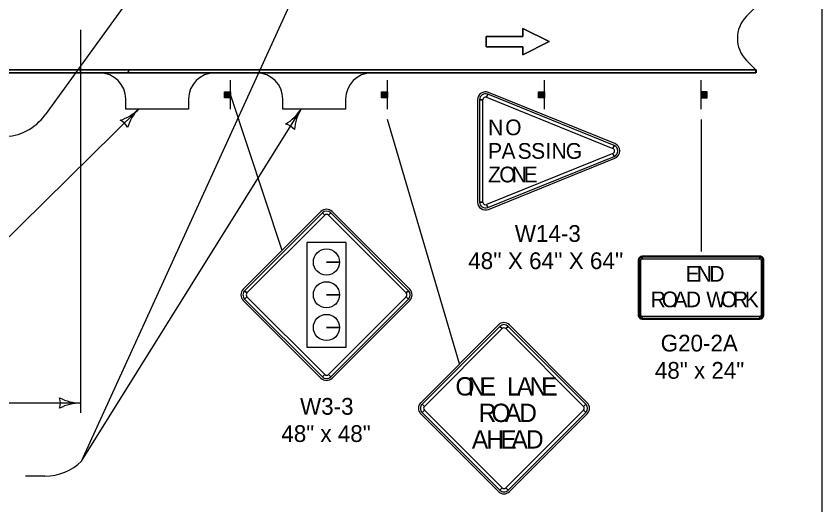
# Model space of a CAD drawing. Extents: x -2134934 to -2122394, y -2139046 to -2137036.
# Drawn here: x -2127867 to -2127097, y -2138081 to -2137614 of the extents above; entities that cross this region are included whole.
import ezdxf

# ---------------------------------------------------------------- set-up
doc = ezdxf.new("R2010")
doc.units = 0
for name, color, linetype in [('Barrier', 7, 'Continuous'), ('BridgeSuperStructureExisting', 7, 'Continuous'), ('Default', 7, 'Continuous'), ('DsnShtPlotIdentification', 7, 'Continuous'), ('DsnShtPlotShape', 7, 'Continuous')]:
    doc.layers.add(name, color=color, linetype=linetype)

msp = doc.modelspace()

# ---------------------------------------------------------------- linework, layer by layer
at = {"layer": 'Barrier'}
for p, q in [((-2127417.35, -2137691.45), (-2127416.18, -2137688.56)), ((-2127294.65, -2137735.69), (-2127415.48, -2137686.82)), ((-2127425.79, -2137693.77), (-2127425.79, -2137791.52)), ((-2127423.92, -2137693.77), (-2127420.79, -2137693.77)), ((-2127295.36, -2137737.43), (-2127296.53, -2137740.33)), ((-2127296.53, -2137744.96), (-2127295.36, -2137747.86)), ((-2127415.48, -2137798.48), (-2127294.65, -2137749.6)), ((-2127420.79, -2137791.52), (-2127423.92, -2137791.52)), ((-2127575.46, -2137800.5), (-2127649.71, -2137874.75)), ((-2127490.61, -2137874.75), (-2127564.86, -2137800.5)), ((-2127416.18, -2137796.74), (-2127417.35, -2137793.84)), ((-2127574.14, -2137801.83), (-2127571.93, -2137804.03)), ((-2127568.39, -2137804.03), (-2127566.18, -2137801.83)), ((-2127156.17, -2137843.14), (-2127268.67, -2137843.14)), ((-2127268.67, -2137845.64), (-2127268.67, -2137844.08)), ((-2127156.17, -2137844.08), (-2127156.17, -2137845.64)), ((-2127557.75, -2137848.72), (-2127570.25, -2137848.72)), ((-2127570.25, -2137848.72), (-2127557.75, -2137848.72)), ((-2127272.42, -2137846.89), (-2127272.42, -2137899.39)), ((-2127271.48, -2137846.89), (-2127269.92, -2137846.89)), ((-2127154.92, -2137846.89), (-2127153.35, -2137846.89)), ((-2127152.42, -2137899.39), (-2127152.42, -2137846.89)), ((-2127646.17, -2137878.28), (-2127648.38, -2137876.07)), ((-2127491.94, -2137876.07), (-2127494.14, -2137878.28)), ((-2127648.38, -2137884.03), (-2127646.17, -2137881.82)), ((-2127557.75, -2137879.97), (-2127570.25, -2137879.97)), ((-2127570.25, -2137879.97), (-2127557.75, -2137879.97)), ((-2127494.14, -2137881.82), (-2127491.94, -2137884.03)), ((-2127649.71, -2137885.35), (-2127575.46, -2137959.6)), ((-2127564.86, -2137959.6), (-2127490.61, -2137885.35)), ((-2127269.92, -2137899.39), (-2127271.48, -2137899.39)), ((-2127153.35, -2137899.39), (-2127154.92, -2137899.39)), ((-2127268.67, -2137902.2), (-2127268.67, -2137900.64)), ((-2127268.67, -2137903.14), (-2127156.17, -2137903.14)), ((-2127156.17, -2137900.64), (-2127156.17, -2137902.2)), ((-2127557.75, -2137911.22), (-2127570.25, -2137911.22)), ((-2127570.25, -2137911.22), (-2127557.75, -2137911.22)), ((-2127405.98, -2137908.8), (-2127480.23, -2137983.04)), ((-2127404.66, -2137910.12), (-2127402.45, -2137912.33)), ((-2127398.91, -2137912.33), (-2127396.7, -2137910.12)), ((-2127321.13, -2137983.04), (-2127395.38, -2137908.8)), ((-2127571.93, -2137956.06), (-2127574.14, -2137958.27)), ((-2127566.18, -2137958.27), (-2127568.39, -2137956.06)), ((-2127476.7, -2137986.58), (-2127478.9, -2137984.37)), ((-2127322.46, -2137984.37), (-2127324.67, -2137986.58)), ((-2127478.9, -2137992.32), (-2127476.7, -2137990.11)), ((-2127324.67, -2137990.11), (-2127322.46, -2137992.32)), ((-2127480.23, -2137993.65), (-2127405.98, -2138067.9)), ((-2127395.38, -2138067.9), (-2127321.13, -2137993.65)), ((-2127402.45, -2138064.36), (-2127404.66, -2138066.57)), ((-2127396.7, -2138066.57), (-2127398.91, -2138064.36))]:
    msp.add_line(p, q, dxfattribs=at)
for points in [[(-2127295.36, -2137737.43), (-2127416.18, -2137688.56), (-2127417.35, -2137691.45), (-2127296.53, -2137740.33), (-2127295.36, -2137737.43)], [(-2127423.92, -2137693.77), (-2127423.92, -2137791.52), (-2127420.79, -2137791.52), (-2127420.79, -2137693.77), (-2127423.92, -2137693.77)], [(-2127416.18, -2137796.74), (-2127295.36, -2137747.86), (-2127296.53, -2137744.96), (-2127417.35, -2137793.84), (-2127416.18, -2137796.74)], [(-2127574.14, -2137801.83), (-2127648.38, -2137876.07), (-2127646.17, -2137878.28), (-2127571.93, -2137804.03), (-2127574.14, -2137801.83)], [(-2127491.94, -2137876.07), (-2127566.18, -2137801.83), (-2127568.39, -2137804.03), (-2127494.14, -2137878.28), (-2127491.94, -2137876.07)], [(-2127551.43, -2137830.1), (-2127588.89, -2137830.1), (-2127588.89, -2137929.99), (-2127551.43, -2137929.99), (-2127551.43, -2137830.1)], [(-2127156.17, -2137844.08), (-2127268.67, -2137844.08), (-2127268.67, -2137845.64), (-2127156.17, -2137845.64), (-2127156.17, -2137844.08)], [(-2127271.48, -2137846.89), (-2127271.48, -2137899.39), (-2127269.92, -2137899.39), (-2127269.92, -2137846.89), (-2127271.48, -2137846.89)], [(-2127153.35, -2137899.39), (-2127153.35, -2137846.89), (-2127154.92, -2137846.89), (-2127154.92, -2137899.39), (-2127153.35, -2137899.39)], [(-2127648.38, -2137884.03), (-2127574.14, -2137958.27), (-2127571.93, -2137956.06), (-2127646.17, -2137881.82), (-2127648.38, -2137884.03)], [(-2127566.18, -2137958.27), (-2127491.94, -2137884.03), (-2127494.14, -2137881.82), (-2127568.39, -2137956.06), (-2127566.18, -2137958.27)], [(-2127268.67, -2137902.2), (-2127156.17, -2137902.2), (-2127156.17, -2137900.64), (-2127268.67, -2137900.64), (-2127268.67, -2137902.2)], [(-2127404.66, -2137910.12), (-2127478.9, -2137984.37), (-2127476.7, -2137986.58), (-2127402.45, -2137912.33), (-2127404.66, -2137910.12)], [(-2127322.46, -2137984.37), (-2127396.7, -2137910.12), (-2127398.91, -2137912.33), (-2127324.67, -2137986.58), (-2127322.46, -2137984.37)], [(-2127478.9, -2137992.32), (-2127404.66, -2138066.57), (-2127402.45, -2138064.36), (-2127476.7, -2137990.11), (-2127478.9, -2137992.32)], [(-2127396.7, -2138066.57), (-2127322.46, -2137992.32), (-2127324.67, -2137990.11), (-2127398.91, -2138064.36), (-2127396.7, -2138066.57)]]:
    msp.add_lwpolyline(points, close=True, dxfattribs=at)
for centre in [(-2127570.25, -2137848.72), (-2127570.25, -2137879.97), (-2127570.25, -2137911.22)]:
    msp.add_circle(centre, 12.5, dxfattribs=at)
for centre, radius, start, end in [((-2127418.29, -2137693.77), 7.5, 67.97571, 179.99985), ((-2127418.29, -2137693.77), 5.62, 67.97571, 179.99985), ((-2127418.29, -2137693.77), 2.5, 67.97571, 179.99985), ((-2127297.47, -2137742.65), 5.62, 292.02456, 67.97541), ((-2127297.47, -2137742.65), 7.5, 292.02456, 67.97598), ((-2127297.47, -2137742.65), 2.5, 292.02456, 67.97541), ((-2127418.29, -2137791.52), 7.5, 179.99985, 292.02456), ((-2127418.29, -2137791.52), 5.62, 179.99985, 292.02456), ((-2127418.29, -2137791.52), 2.5, 179.99985, 292.02456), ((-2127570.16, -2137805.8), 7.5, 44.99999, 134.99974), ((-2127570.16, -2137805.8), 5.62, 44.99999, 134.99974), ((-2127570.16, -2137805.8), 2.5, 44.99999, 134.99974), ((-2127268.67, -2137846.89), 3.75, 90.00021, 179.99985), ((-2127268.67, -2137846.89), 2.81, 90.00021, 179.99985), ((-2127268.67, -2137846.89), 1.25, 90.00021, 179.99985), ((-2127156.17, -2137846.89), 3.75, 0, 90.00021), ((-2127156.17, -2137846.89), 2.81, 0, 90.00021), ((-2127156.17, -2137846.89), 1.25, 0, 90.00021), ((-2127644.41, -2137880.05), 7.5, 134.99974, 224.99995), ((-2127644.41, -2137880.05), 5.62, 134.99974, 224.99995), ((-2127495.91, -2137880.05), 5.62, 315.00016, 44.9998), ((-2127495.91, -2137880.05), 7.5, 315.00016, 44.9998), ((-2127644.41, -2137880.05), 2.5, 134.99974, 224.99995), ((-2127495.91, -2137880.05), 2.5, 315.00016, 44.9998), ((-2127268.67, -2137899.39), 3.75, 179.99985, 270.00006), ((-2127268.67, -2137899.39), 2.81, 179.99985, 270.00006), ((-2127268.67, -2137899.39), 1.25, 179.99985, 270.00006), ((-2127156.17, -2137899.39), 3.75, 270.00006, 0.00027), ((-2127156.17, -2137899.39), 2.81, 270.00006, 0.00027), ((-2127156.17, -2137899.39), 1.25, 270.00006, 0.00027), ((-2127400.68, -2137914.1), 7.5, 44.99999, 134.99974), ((-2127400.68, -2137914.1), 5.62, 44.99999, 134.99974), ((-2127400.68, -2137914.1), 2.5, 44.99999, 134.99974), ((-2127570.16, -2137954.29), 7.5, 224.99995, 315.00016), ((-2127570.16, -2137954.29), 5.62, 224.99995, 315.00016), ((-2127570.16, -2137954.29), 2.5, 224.99995, 315.00016), ((-2127474.93, -2137988.35), 7.5, 134.99974, 224.99995), ((-2127474.93, -2137988.35), 5.62, 134.99974, 224.99995), ((-2127326.44, -2137988.35), 5.62, 315.00016, 44.9998), ((-2127326.44, -2137988.35), 7.5, 315.00016, 44.9998), ((-2127474.93, -2137988.35), 2.5, 134.99974, 224.99995), ((-2127326.44, -2137988.35), 2.5, 315.00016, 44.9998), ((-2127400.68, -2138062.59), 7.5, 224.99995, 315.00016), ((-2127400.68, -2138062.59), 5.62, 224.99995, 315.00016), ((-2127400.68, -2138062.59), 2.5, 224.99995, 315.00016)]:
    msp.add_arc(centre, radius, start, end, dxfattribs=at)
at = {"layer": 'BridgeSuperStructureExisting'}
for p, q in [((-2127686.42, -2137497.23), (-2127838.98, -2137708.29)), ((-2127804.12, -2138038.74), (-2127571.87, -2137530.07)), ((-2127168.91, -2137613.95), (-2127151.33, -2137596.37)), ((-2127805.12, -2137627.09), (-2127805.12, -2137992.63)), ((-2127160.12, -2137665.16), (-2127168.91, -2137656.37)), ((-2127168.9, -2137656.38), (-2127160.12, -2137665.16)), ((-2128470.12, -2137665.16), (-2127160.12, -2137665.16)), ((-2127786.92, -2137668.16), (-2127676.92, -2137668.16)), ((-2127636.92, -2137668.16), (-2127526.92, -2137668.16)), ((-2127661.96, -2137702.66), (-2127661.96, -2137675.16)), ((-2127511.96, -2137702.66), (-2127511.96, -2137675.16)), ((-2127361.96, -2137702.66), (-2127361.96, -2137675.16)), ((-2127212.15, -2137702.66), (-2127212.15, -2137675.16)), ((-2127667.28, -2137691.8), (-2127667.28, -2137686.21)), ((-2127666.96, -2137686.21), (-2127666.96, -2137691.8)), ((-2127666.74, -2137691.8), (-2127666.74, -2137686.21)), ((-2127666.42, -2137686.21), (-2127666.42, -2137691.8)), ((-2127666.19, -2137691.8), (-2127666.21, -2137686.21)), ((-2127665.78, -2137686.21), (-2127665.76, -2137691.8)), ((-2127665.56, -2137691.8), (-2127665.56, -2137686.21)), ((-2127665.13, -2137686.21), (-2127665.13, -2137691.8)), ((-2127664.75, -2137691.8), (-2127664.75, -2137686.21)), ((-2127664.43, -2137686.21), (-2127664.41, -2137691.8)), ((-2127664.21, -2137691.8), (-2127664.21, -2137686.21)), ((-2127663.94, -2137686.21), (-2127663.94, -2137691.8)), ((-2127663.61, -2137691.8), (-2127663.61, -2137686.21)), ((-2127663.4, -2137686.21), (-2127663.4, -2137691.8)), ((-2127663.18, -2137691.8), (-2127663.18, -2137686.21)), ((-2127662.91, -2137686.21), (-2127662.91, -2137691.8)), ((-2127662.65, -2137691.8), (-2127662.65, -2137686.21)), ((-2127662.37, -2137686.21), (-2127662.37, -2137691.8)), ((-2127612.59, -2137837.62), (-2127661.96, -2137688.91)), ((-2127517.28, -2137691.8), (-2127517.28, -2137686.21)), ((-2127516.96, -2137686.21), (-2127516.96, -2137691.8)), ((-2127516.74, -2137691.8), (-2127516.74, -2137686.21)), ((-2127516.42, -2137686.21), (-2127516.42, -2137691.8)), ((-2127516.19, -2137691.8), (-2127516.21, -2137686.21)), ((-2127515.78, -2137686.21), (-2127515.76, -2137691.8)), ((-2127515.56, -2137691.8), (-2127515.56, -2137686.21)), ((-2127515.13, -2137686.21), (-2127515.13, -2137691.8)), ((-2127514.75, -2137691.8), (-2127514.75, -2137686.21)), ((-2127514.43, -2137686.21), (-2127514.41, -2137691.8)), ((-2127514.21, -2137691.8), (-2127514.21, -2137686.21)), ((-2127513.94, -2137686.21), (-2127513.94, -2137691.8)), ((-2127513.61, -2137691.8), (-2127513.61, -2137686.21)), ((-2127513.4, -2137686.21), (-2127513.4, -2137691.8)), ((-2127513.18, -2137691.8), (-2127513.18, -2137686.21)), ((-2127512.91, -2137686.21), (-2127512.91, -2137691.8)), ((-2127512.65, -2137691.8), (-2127512.65, -2137686.21)), ((-2127512.37, -2137686.21), (-2127512.37, -2137691.8)), ((-2127367.28, -2137691.8), (-2127367.28, -2137686.21)), ((-2127366.96, -2137686.21), (-2127366.96, -2137691.8)), ((-2127366.74, -2137691.8), (-2127366.74, -2137686.21)), ((-2127366.42, -2137686.21), (-2127366.42, -2137691.8)), ((-2127366.19, -2137691.8), (-2127366.21, -2137686.21)), ((-2127365.78, -2137686.21), (-2127365.76, -2137691.8)), ((-2127365.56, -2137691.8), (-2127365.56, -2137686.21)), ((-2127365.13, -2137686.21), (-2127365.13, -2137691.8)), ((-2127364.75, -2137691.8), (-2127364.75, -2137686.21)), ((-2127364.43, -2137686.21), (-2127364.41, -2137691.8)), ((-2127364.21, -2137691.8), (-2127364.21, -2137686.21)), ((-2127363.94, -2137686.21), (-2127363.94, -2137691.8)), ((-2127363.61, -2137691.8), (-2127363.61, -2137686.21)), ((-2127363.4, -2137686.21), (-2127363.4, -2137691.8)), ((-2127363.18, -2137691.8), (-2127363.18, -2137686.21)), ((-2127362.91, -2137686.21), (-2127362.91, -2137691.8)), ((-2127362.65, -2137691.8), (-2127362.65, -2137686.21)), ((-2127362.37, -2137686.21), (-2127362.37, -2137691.8)), ((-2127211.73, -2137686.21), (-2127211.73, -2137691.8)), ((-2127211.45, -2137691.8), (-2127211.45, -2137686.21)), ((-2127211.19, -2137686.21), (-2127211.19, -2137691.8)), ((-2127210.93, -2137691.8), (-2127210.93, -2137686.21)), ((-2127210.7, -2137686.21), (-2127210.7, -2137691.8)), ((-2127210.5, -2137691.8), (-2127210.5, -2137686.21)), ((-2127210.16, -2137686.21), (-2127210.16, -2137691.8)), ((-2127209.9, -2137691.8), (-2127209.9, -2137686.21)), ((-2127209.67, -2137686.21), (-2127209.69, -2137691.8)), ((-2127209.35, -2137691.8), (-2127209.35, -2137686.21)), ((-2127208.98, -2137686.21), (-2127208.98, -2137691.8)), ((-2127208.55, -2137691.8), (-2127208.55, -2137686.21)), ((-2127208.32, -2137686.21), (-2127208.34, -2137691.8)), ((-2127207.91, -2137691.8), (-2127207.89, -2137686.21)), ((-2127207.68, -2137686.21), (-2127207.68, -2137691.8)), ((-2127207.36, -2137691.8), (-2127207.36, -2137686.21)), ((-2127207.14, -2137686.21), (-2127207.14, -2137691.8)), ((-2127206.82, -2137691.8), (-2127206.82, -2137686.21)), ((-2127937.83, -2137887.94), (-2127749.7, -2137702.65)), ((-2127804.12, -2138038.74), (-2127594.47, -2137702.65)), ((-2127443.11, -2137945.92), (-2127511.96, -2137712.66)), ((-2127211.96, -2137838.71), (-2127211.96, -2137712.66)), ((-2127805.12, -2137983.33), (-2128464.54, -2137983.33)), ((-2127839.21, -2138053.11), (-2127857.67, -2138053.11))]:
    msp.add_line(p, q, dxfattribs=at)
for points in [[(-2127417.52, -2137633.32), (-2127417.52, -2137643.32), (-2127382.52, -2137643.32), (-2127382.52, -2137650.82), (-2127357.52, -2137638.32), (-2127382.52, -2137625.82), (-2127382.52, -2137633.32)], [(-2127662.05, -2137686.21), (-2127662.05, -2137691.84), (-2127667.68, -2137691.84), (-2127667.68, -2137686.21)], [(-2127512.05, -2137686.21), (-2127512.05, -2137691.84), (-2127517.68, -2137691.84), (-2127517.68, -2137686.21)], [(-2127362.05, -2137686.21), (-2127362.05, -2137691.84), (-2127367.68, -2137691.84), (-2127367.68, -2137686.21)], [(-2127212.05, -2137686.21), (-2127212.05, -2137691.84), (-2127206.43, -2137691.84), (-2127206.43, -2137686.21)]]:
    msp.add_lwpolyline(points, close=True, dxfattribs=at)
for points in [[(-2127382.52, -2137633.32), (-2127382.52, -2137625.82), (-2127357.52, -2137638.32), (-2127382.52, -2137650.82), (-2127382.52, -2137643.32), (-2127417.52, -2137643.32), (-2127417.52, -2137633.32), (-2127382.52, -2137633.32)], [(-2127701.92, -2137693.16), (-2127701.92, -2137702.65), (-2127761.92, -2137702.65), (-2127761.92, -2137693.16)], [(-2127551.92, -2137693.16), (-2127551.92, -2137702.65), (-2127611.92, -2137702.65), (-2127611.92, -2137693.16)]]:
    msp.add_lwpolyline(points, dxfattribs=at)
for centre, radius, start, end in [((-2127147.69, -2137635.16), 30, 135, 225), ((-2127147.69, -2137635.16), 30, 135, 225), ((-2127786.92, -2137693.16), 25, 0, 90), ((-2127676.92, -2137693.16), 25, 90, 180), ((-2127636.92, -2137693.16), 25, 0, 90), ((-2127526.92, -2137693.16), 25, 90, 180), ((-2127879.5, -2137678.99), 50, 270, 324.13795), ((-2127839.21, -2138003.11), 50, 270, 314.56349)]:
    msp.add_arc(centre, radius, start, end, dxfattribs=at)
at = {"layer": 'Default'}
msp.add_lwpolyline([(-2130231.95, -2137035.95), (-2127096.96, -2137035.95), (-2127096.96, -2139045.94), (-2130231.95, -2139045.94)], close=True, dxfattribs=at)
at = {"layer": 'DsnShtPlotIdentification'}
for p, q in [((-2128660.12, -2137665.16), (-2127159.5, -2137665.16)), ((-2127805.12, -2137665.16), (-2128280.26, -2137665.16)), ((-2128278.09, -2137668.16), (-2127805.12, -2137668.16)), ((-2127805.12, -2137668.16), (-2127805.12, -2137665.16)), ((-2127805.12, -2137665.16), (-2127805.12, -2137668.16)), ((-2127758.7, -2137665.16), (-2127805.12, -2137665.16)), ((-2127805.12, -2137668.16), (-2127759.9, -2137668.16)), ((-2127759.9, -2137668.16), (-2127758.7, -2137665.16)), ((-2127758.7, -2137665.16), (-2127759.9, -2137668.16)), ((-2127759.9, -2137668.16), (-2127160.12, -2137668.16)), ((-2127160.12, -2137665.16), (-2127758.7, -2137665.16)), ((-2127160.12, -2137668.16), (-2127160.12, -2137665.16)), ((-2127159.5, -2137668.16), (-2127159.5, -2137665.16))]:
    msp.add_line(p, q, dxfattribs=at)
for points in [[(-2127160.12, -2137665.16), (-2128470.12, -2137665.16)], [(-2127160.12, -2137668.16), (-2128470.12, -2137668.16)]]:
    msp.add_lwpolyline(points, dxfattribs=at)
at = {"layer": 'DsnShtPlotShape'}
for centre, radius, start, end in [((-2127779.89, -2137672.74), 42.5, 287.19716, 315.26965), ((-2127719.51, -2137732.56), 42.5, 135.26965, 163.34214), ((-2127630.52, -2137680.15), 42.5, 299.97081, 328.0433), ((-2127558.41, -2137725.14), 42.5, 148.0433, 176.11579), ((-2127774.78, -2137727.96), 16.42, 27.53629, 63.003), ((-2127613.33, -2137732.88), 16.42, 40.30995, 75.77665), ((-2127840.75, -2137983.33), 16.42, 342.26665, 17.73335), ((-2127805.12, -2137940.83), 42.5, 241.92751, 270), ((-2127805.12, -2138025.83), 42.5, 90, 118.07249)]:
    msp.add_arc(centre, radius, start, end, dxfattribs=at)

# ---------------------------------------------------------------- texts
at = {"layer": 'Barrier'}
for s, height, p in [('N', 15, (-2127415.82, -2137727.65)), ('O', 15, (-2127399.48, -2137727.65)), ('P', 15, (-2127415.82, -2137750.15)), ('A', 15, (-2127402.93, -2137750.15)), ('S', 15, (-2127387.58, -2137750.15)), ('S', 15, (-2127374.69, -2137750.15)), ('I', 15, (-2127361.09, -2137750.15)), ('N', 15, (-2127355.23, -2137750.15)), ('G', 15, (-2127341.64, -2137750.15)), ('Z', 15, (-2127415.82, -2137772.65)), ('O', 15, (-2127405.09, -2137772.65)), ('N', 15, (-2127393.26, -2137772.65)), ('E', 15, (-2127381.89, -2137772.65)), ('W14-3', 16, (-2127390.28, -2137829.48)), ("48'' X 64'' X 64''", 16, (-2127434.77, -2137855.47)), ('E', 15, (-2127227.09, -2137867.51)), ('N', 15, (-2127216.47, -2137867.51)), ('D', 15, (-2127204.39, -2137867.51)), ('R', 15, (-2127260.56, -2137891.89)), ('O', 15, (-2127249.87, -2137891.89)), ('A', 15, (-2127238.72, -2137891.89)), ('D', 15, (-2127226.86, -2137891.89)), ('W', 15, (-2127207.4, -2137891.89)), ('O', 15, (-2127193.67, -2137891.89)), ('R', 15, (-2127181.9, -2137891.89)), ('K', 15, (-2127170.61, -2137891.89)), ('G20-2A', 16, (-2127250.95, -2137934.14)), ('48" x 24"', 16, (-2127256.48, -2137960.14)), ('O', 17.5, (-2127446.97, -2137976.16)), ('N', 17.5, (-2127435.19, -2137976.16)), ('E', 17.5, (-2127423.96, -2137976.16)), ('L', 17.5, (-2127397.71, -2137976.16)), ('A', 17.5, (-2127388.52, -2137976.16)), ('N', 17.5, (-2127376.25, -2137976.16)), ('E', 17.5, (-2127365.02, -2137976.16)), ('W3-3', 16, (-2127595.45, -2137994.51)), ('R', 17.5, (-2127424.86, -2138001.47)), ('O', 17.5, (-2127412.57, -2138001.47)), ('A', 17.5, (-2127399.73, -2138001.47)), ('D', 17.5, (-2127386.08, -2138001.47)), ('48" x 48"', 16, (-2127613.33, -2138020.51)), ('A', 17.5, (-2127431.3, -2138026.78)), ('H', 17.5, (-2127417.43, -2138026.78)), ('E', 17.5, (-2127404.21, -2138026.78)), ('A', 17.5, (-2127393.5, -2138026.78)), ('D', 17.5, (-2127379.64, -2138026.78))]:
    msp.add_text(s, height=height, dxfattribs=at).set_placement(p)

doc.saveas('drawing.dxf')
